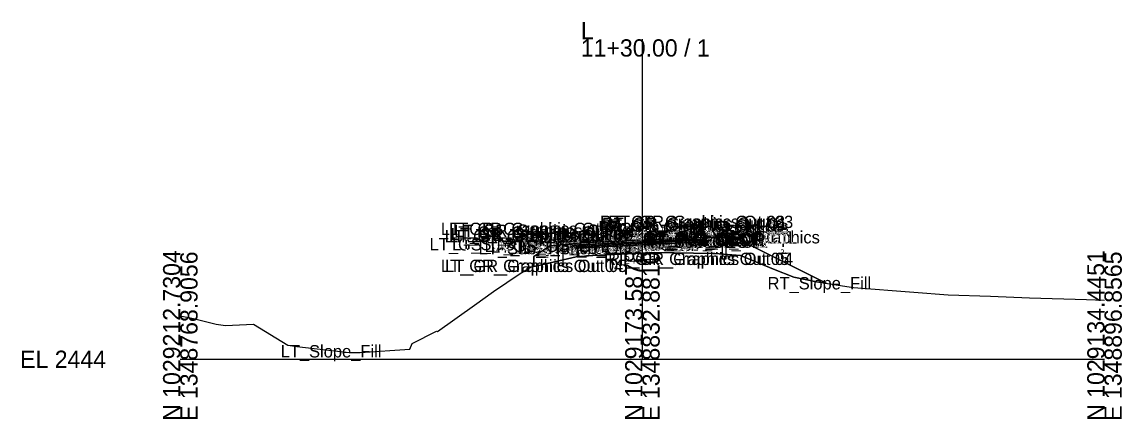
# Model space of a CAD drawing. Extents: x -26 to 1453, y -10 to 4527.
# Drawn here: x 1274.3 to 1452.8, y 2490.3 to 2554.7 of the extents above; entities that cross this region are included whole.
import ezdxf

# ---------------------------------------------------------------- set-up
doc = ezdxf.new("R2010")
doc.units = 0
for name, color, linetype in [('Default', 7, 'Continuous'), ('Exist Cross Section Cell', 7, 'Continuous'), ('Exist XS Center Line Elevation Label', 7, 'Continuous'), ('Exist XS Ground Line', 7, 'Continuous'), ('Old_Level_63', 7, 'Continuous'), ('Prop CMT Guardrail Graphics', 7, 'Continuous'), ('Prop CMT Pvmt Course 1', 7, 'Continuous'), ('Prop CMT Pvmt Course 2', 7, 'Continuous'), ('Prop CMT Pvmt Course 3', 7, 'Continuous'), ('Prop CMT Pvmt Surface', 7, 'Continuous'), ('Prop CMT Pvmt Surface Overlay', 7, 'Continuous'), ('Prop CMT Pvmt Surface Shoulder', 7, 'Continuous'), ('Prop CMT Shld Paved Course 1', 7, 'Continuous'), ('Prop CMT Shld Paved Course 2', 7, 'Continuous'), ('Prop CMT Shld Paved Course 3', 7, 'Continuous'), ('Prop CMT Slope Grass', 7, 'Continuous'), ('Prop CMT Subgrade Earthwork', 7, 'Continuous'), ('Prop XS Earthwork Shape', 7, 'Continuous'), ('Prop XS EOT Tick Mark', 7, 'Continuous'), ('Prop XS SE Text', 7, 'Continuous'), ('Prop XS Side Slope Text', 7, 'Continuous')]:
    doc.layers.add(name, color=color, linetype=linetype)

msp = doc.modelspace()

# ---------------------------------------------------------------- linework, layer by layer
at = {"layer": 'Exist Cross Section Cell'}
for p, q in [((1375, 2500), (1375, 2551.91)), ((1300, 2500), (1375, 2500)), ((1375, 2500), (1450, 2500))]:
    msp.add_line(p, q, dxfattribs=at)
at = {"layer": 'Exist XS Ground Line'}
msp.add_lwpolyline([(1300, 2507.06), (1302.12, 2506.6), (1305.8, 2505.7), (1307.34, 2505.45), (1311.88, 2505.67), (1317.45, 2502.26), (1318.9, 2502.09), (1327.42, 2501.09), (1329.19, 2501.12), (1337.24, 2501.64), (1337.63, 2502.55), (1341.56, 2504.53), (1341.76, 2504.51), (1347.75, 2508.75), (1350.82, 2511), (1355.16, 2513.9), (1356.93, 2514.97), (1357.9, 2515.18), (1364.24, 2516.64), (1366.95, 2516.83), (1368.03, 2516.9), (1375, 2517.22), (1376.97, 2517.3), (1386.47, 2517.18), (1386.78, 2517.15), (1390.93, 2516.82), (1396.26, 2514.64), (1399.6, 2513.31), (1403.26, 2512.58), (1409.28, 2511.64), (1419.03, 2510.86), (1424.6, 2510.45), (1431.5, 2510.21), (1437.8, 2509.97), (1447.09, 2509.71), (1450, 2509.61)], dxfattribs=at)
at = {"layer": 'Prop CMT Guardrail Graphics'}
for points in [[(1361.4, 2515.15), (1361.4, 2521.15)], [(1361.4, 2521.15), (1362.73, 2521.15), (1363, 2520.85)], [(1388.6, 2522.29), (1387.27, 2522.29), (1387, 2521.99)], [(1387, 2521.99), (1387.27, 2521.7)], [(1387.27, 2521.7), (1387, 2521.41)], [(1387, 2521.41), (1387.27, 2521.12), (1387.94, 2521.12)], [(1387.94, 2521.12), (1387.94, 2516.29)], [(1388.6, 2516.29), (1388.6, 2522.29)], [(1363, 2520.27), (1362.73, 2519.98), (1362.06, 2519.98)], [(1362.06, 2519.98), (1362.06, 2515.15)], [(1363, 2520.85), (1362.73, 2520.56)], [(1362.73, 2520.56), (1363, 2520.27)], [(1387.94, 2516.29), (1388.6, 2516.29)], [(1362.06, 2515.15), (1361.4, 2515.15)]]:
    msp.add_lwpolyline(points, dxfattribs=at)
at = {"layer": 'Prop CMT Pvmt Course 1'}
for points in [[(1375, 2519.31), (1365, 2518.81)], [(1375, 2519.31), (1385, 2519.81)], [(1385, 2519.56), (1375, 2519.06)], [(1375, 2519.18), (1375, 2519.31)], [(1375, 2519.18), (1375, 2519.31)], [(1375, 2519.06), (1375, 2519.18), (1375, 2519.18)], [(1375, 2519.06), (1375, 2519.18), (1375, 2519.18)], [(1385, 2519.81), (1385, 2519.56)], [(1365, 2518.56), (1375, 2519.06)], [(1365, 2518.81), (1365, 2518.56)]]:
    msp.add_lwpolyline(points, dxfattribs=at)
at = {"layer": 'Prop CMT Pvmt Course 2'}
for points in [[(1375, 2519.06), (1385, 2519.56)], [(1385, 2519.31), (1375, 2518.81)], [(1385, 2519.56), (1385, 2519.31)], [(1375, 2519.06), (1365, 2518.56)], [(1365, 2518.31), (1375, 2518.81)], [(1365, 2518.56), (1365, 2518.31)], [(1375, 2518.81), (1375, 2519.06)], [(1375, 2518.81), (1375, 2519.06)]]:
    msp.add_lwpolyline(points, dxfattribs=at)
at = {"layer": 'Prop CMT Pvmt Course 3'}
for points in [[(1375, 2518.81), (1385, 2519.31)], [(1385, 2519.31), (1385, 2519.06)], [(1375, 2518.81), (1365, 2518.31)], [(1365, 2518.06), (1375, 2518.56)], [(1365, 2518.31), (1365, 2518.06)], [(1385, 2519.06), (1375, 2518.56)], [(1375, 2518.56), (1375, 2518.81)], [(1375, 2518.56), (1375, 2518.81)]]:
    msp.add_lwpolyline(points, dxfattribs=at)
at = {"layer": 'Prop CMT Pvmt Surface'}
for points in [[(1375, 2519.31), (1365, 2518.81)], [(1375, 2519.31), (1385, 2519.81)]]:
    msp.add_lwpolyline(points, dxfattribs=at)
at = {"layer": 'Prop CMT Pvmt Surface Overlay'}
for points in [[(1375, 2519.31), (1365, 2518.81)], [(1375, 2519.31), (1385, 2519.81)]]:
    msp.add_lwpolyline(points, dxfattribs=at)
at = {"layer": 'Prop CMT Pvmt Surface Shoulder'}
for points in [[(1385, 2519.81), (1385, 2519.81)], [(1365, 2518.81), (1365, 2518.81)]]:
    msp.add_lwpolyline(points, dxfattribs=at)
at = {"layer": 'Prop CMT Shld Paved Course 1'}
for points in [[(1385, 2519.81), (1385, 2519.81), (1385.24, 2519.57)], [(1385, 2519.56), (1385, 2519.81)], [(1385.24, 2519.57), (1385, 2519.56)], [(1365, 2518.81), (1365, 2518.81), (1364.74, 2518.54)], [(1364.74, 2518.54), (1365, 2518.56)], [(1365, 2518.56), (1365, 2518.81)]]:
    msp.add_lwpolyline(points, dxfattribs=at)
at = {"layer": 'Prop CMT Shld Paved Course 2'}
for points in [[(1385, 2519.56), (1385.24, 2519.57), (1385.48, 2519.33)], [(1385, 2519.31), (1385, 2519.56)], [(1385.48, 2519.33), (1385, 2519.31)], [(1365, 2518.56), (1364.74, 2518.54), (1364.47, 2518.28)], [(1364.47, 2518.28), (1365, 2518.31)], [(1365, 2518.31), (1365, 2518.56)]]:
    msp.add_lwpolyline(points, dxfattribs=at)
at = {"layer": 'Prop CMT Shld Paved Course 3'}
for points in [[(1385, 2519.31), (1385.48, 2519.33)], [(1385, 2519.06), (1385, 2519.31)], [(1385.48, 2519.33), (1385.48, 2519.33)], [(1385.48, 2519.33), (1385.72, 2519.09)], [(1364.47, 2518.28), (1364.21, 2518.02)], [(1364.21, 2518.02), (1365, 2518.06)], [(1365, 2518.31), (1364.47, 2518.28)], [(1364.47, 2518.28), (1364.47, 2518.28)], [(1365, 2518.06), (1365, 2518.31)], [(1385.72, 2519.09), (1385, 2519.06)]]:
    msp.add_lwpolyline(points, dxfattribs=at)
at = {"layer": 'Prop CMT Slope Grass'}
for points in [[(1385, 2519.81), (1387, 2519.79)], [(1387, 2519.79), (1390, 2519.76)], [(1390, 2519.76), (1404.85, 2512.33)], [(1360, 2518.41), (1357.38, 2516.66)], [(1363, 2518.65), (1360, 2518.41)], [(1365, 2518.81), (1363, 2518.65)], [(1357.38, 2516.66), (1357.38, 2515.06)]]:
    msp.add_lwpolyline(points, dxfattribs=at)
at = {"layer": 'Prop CMT Subgrade Earthwork'}
for points in [[(1385.72, 2519.09), (1386.42, 2519.79)], [(1364.21, 2518.02), (1363.54, 2518.69)], [(1365, 2518.06), (1364.21, 2518.02)], [(1375, 2518.56), (1365, 2518.06)], [(1375, 2518.56), (1385, 2519.06)], [(1385, 2519.06), (1385.72, 2519.09)]]:
    msp.add_lwpolyline(points, dxfattribs=at)
at = {"layer": 'Prop XS Earthwork Shape'}
for points in [[(1375, 2518.56), (1385, 2519.06), (1385.72, 2519.09), (1386.42, 2519.79), (1387, 2519.79), (1390, 2519.76), (1404.85, 2512.33), (1403.26, 2512.58), (1399.6, 2513.31), (1396.26, 2514.64), (1390.93, 2516.82), (1386.78, 2517.15), (1386.47, 2517.18), (1376.97, 2517.3), (1375, 2517.22), (1368.03, 2516.9), (1366.95, 2516.83), (1364.24, 2516.64), (1357.9, 2515.18), (1357.38, 2515.06), (1357.38, 2516.66), (1360, 2518.41), (1363, 2518.65), (1363.54, 2518.69), (1364.21, 2518.02), (1365, 2518.06)], [(1364.21, 2518.02), (1363.54, 2518.69), (1363, 2518.65), (1360, 2518.41), (1357.38, 2516.66), (1357.38, 2515.06), (1357.9, 2515.18), (1364.24, 2516.64), (1366.95, 2516.83), (1368.03, 2516.9), (1375, 2517.22), (1376.97, 2517.3), (1386.47, 2517.18), (1386.78, 2517.15), (1390.93, 2516.82), (1396.26, 2514.64), (1399.6, 2513.31), (1403.26, 2512.58), (1404.85, 2512.33), (1390, 2519.76), (1387, 2519.79), (1386.42, 2519.79), (1385.72, 2519.09), (1385, 2519.06), (1375, 2518.56), (1365, 2518.06)]]:
    msp.add_lwpolyline(points, close=True, dxfattribs=at)
at = {"layer": 'Prop XS EOT Tick Mark'}
for points in [[(1365, 2518.81), (1365, 2519.81)], [(1385, 2519.81), (1385, 2520.81)]]:
    msp.add_lwpolyline(points, dxfattribs=at)

# ---------------------------------------------------------------- texts
at = {"layer": 'Default'}
msp.add_text('-', height=0.0001, dxfattribs=at).set_placement((1300, 2500))
at = {"layer": 'Exist Cross Section Cell'}
for s, p in [('L', (1365, 2551.91)), ('11+30.00 / 1', (1365, 2549.11)), ('EL 2444', (1274, 2498.6))]:
    msp.add_text(s, height=2.8, dxfattribs=at).set_placement(p)
for s, p in [('N 1029212.7304', (1300, 2490)), ('E 1348768.9056', (1302.8, 2490)), ('N 1029173.5878', (1375, 2490)), ('E 1348832.8810', (1377.8, 2490)), ('N 1029134.4451', (1450, 2490)), ('E 1348896.8565', (1452.8, 2490))]:
    msp.add_text(s, height=2.8, rotation=90, dxfattribs=at).set_placement(p)
at = {"layer": 'Exist XS Center Line Elevation Label'}
msp.add_text('2461.22', height=1.23, dxfattribs=at).set_placement((1372.07, 2515.49))
at = {"layer": 'Old_Level_63'}
for s, p in [('RT_GR_Graphics Out 02', (1368.12, 2521.29)), ('RT_GR_Graphics Out 09', (1368.12, 2520.7)), ('RT_GR_Graphics Out 01', (1368.42, 2520.99)), ('RT_GR_Graphics Out 03', (1369.45, 2521.29)), ('LT_GR_Graphics Out 03', (1342.29, 2520.15)), ('LT_GR_Graphics Out 06', (1342.91, 2518.98)), ('LT_GR_Graphics Out 02', (1343.63, 2520.15)), ('LT_GR_Graphics Out 09', (1343.63, 2519.56)), ('LT_GR_Graphics Out 07', (1343.63, 2518.98)), ('LT_GR_Graphics Out 08', (1343.9, 2519.27)), ('LT_GR_Graphics Out 01', (1344.46, 2519.85)), ('RT_GS_OS_GR_Face_Graphics', (1364.41, 2518.79)), ('RT_Sub_Trench_Out_DLT', (1366.94, 2518.79)), ('RT_GR_Graphics Out 08', (1367.85, 2520.41)), ('RT_GR_Graphics Out 07', (1368.12, 2520.12)), ('RT_GR_Graphics Out 06', (1368.74, 2520.12)), ('RT_TM_OEOT', (1375.9, 2519.81)), ('LT_GS_OS_GR_Face_Graphics', (1340.46, 2517.65)), ('LT_Sub_Trench_Out_DLT', (1344.1, 2517.69)), ('LT_Sub_Trench_Out', (1348.41, 2517.02)), ('LT_GS_OS_CTL', (1349.37, 2517.41)), ('LT_PS3_Shelf_Out', (1350.46, 2517.28)), ('LT_PS3_OEOP', (1354.71, 2517.28)), ('LT_PS2_OEOP', (1354.97, 2517.54)), ('LT_Sub_OEOT', (1355.08, 2517.06)), ('LT_PV2_OEOT', (1355.17, 2517.56)), ('LT_PV3_OEOT', (1355.17, 2517.31)), ('LT_PV1_OEOT', (1355.74, 2517.81)), ('LT_PS1_OEOP', (1355.8, 2517.81)), ('LT_TM_OEOT', (1355.94, 2518.81)), ('RT_PV1_OEEOP_W', (1362.94, 2518.18)), ('LT_PV1_OEEOP_W', (1362.98, 2518.18)), ('RT_Sub_OEEOP', (1364.17, 2517.56)), ('LT_Sub_OEEOP', (1364.21, 2517.56)), ('RT_PV2_OEEOP', (1364.26, 2518.06)), ('RT_PV3_OEEOP', (1364.26, 2517.81)), ('LT_PV2_OEEOP', (1364.31, 2518.06)), ('LT_PV3_OEEOP', (1364.31, 2517.81)), ('PV1_PGL_W', (1367.58, 2518.18)), ('PV1_PGL', (1369.47, 2518.31)), ('RT_Sub_Trench_Out', (1369.87, 2518.09)), ('RT_PS3_Shelf_Out', (1371.41, 2518.33)), ('RT_Sub_OEOT', (1375.03, 2518.06)), ('RT_PV2_OEOT', (1375.13, 2518.56)), ('RT_PV3_OEOT', (1375.13, 2518.31)), ('RT_PS2_OEOP', (1375.43, 2518.57)), ('RT_PS3_OEOP', (1375.67, 2518.33)), ('RT_PV1_OEOT', (1375.69, 2518.81)), ('RT_PS1_OEOP', (1375.76, 2518.81)), ('RT_GS_OS_CTL', (1379.32, 2518.76)), ('RT_GR_Graphics Out 05', (1368.79, 2515.29)), ('RT_GR_Graphics Out 04', (1369.45, 2515.29)), ('LT_GR_Graphics Out 04', (1342.29, 2514.15)), ('LT_GR_Graphics Out 05', (1342.96, 2514.15)), ('RT_Slope_Fill', (1395.32, 2511.33)), ('LT_Slope_Fill', (1316.29, 2500.29))]:
    msp.add_text(s, height=2, dxfattribs=at).set_placement(p)
at = {"layer": 'Prop XS SE Text'}
for p in [(1368.2, 2519.97), (1378.2, 2520.47)]:
    msp.add_text('0.050', height=1, rotation=2.8624, dxfattribs=at).set_placement(p)
at = {"layer": 'Prop XS Side Slope Text'}
for s, rotation, p in [('1.5:1', 33.6901, (1357.27, 2517.5)), ('2:1', 333.4349, (1397.05, 2517.07))]:
    msp.add_text(s, height=1, rotation=rotation, dxfattribs=at).set_placement(p)

doc.saveas('drawing.dxf')
